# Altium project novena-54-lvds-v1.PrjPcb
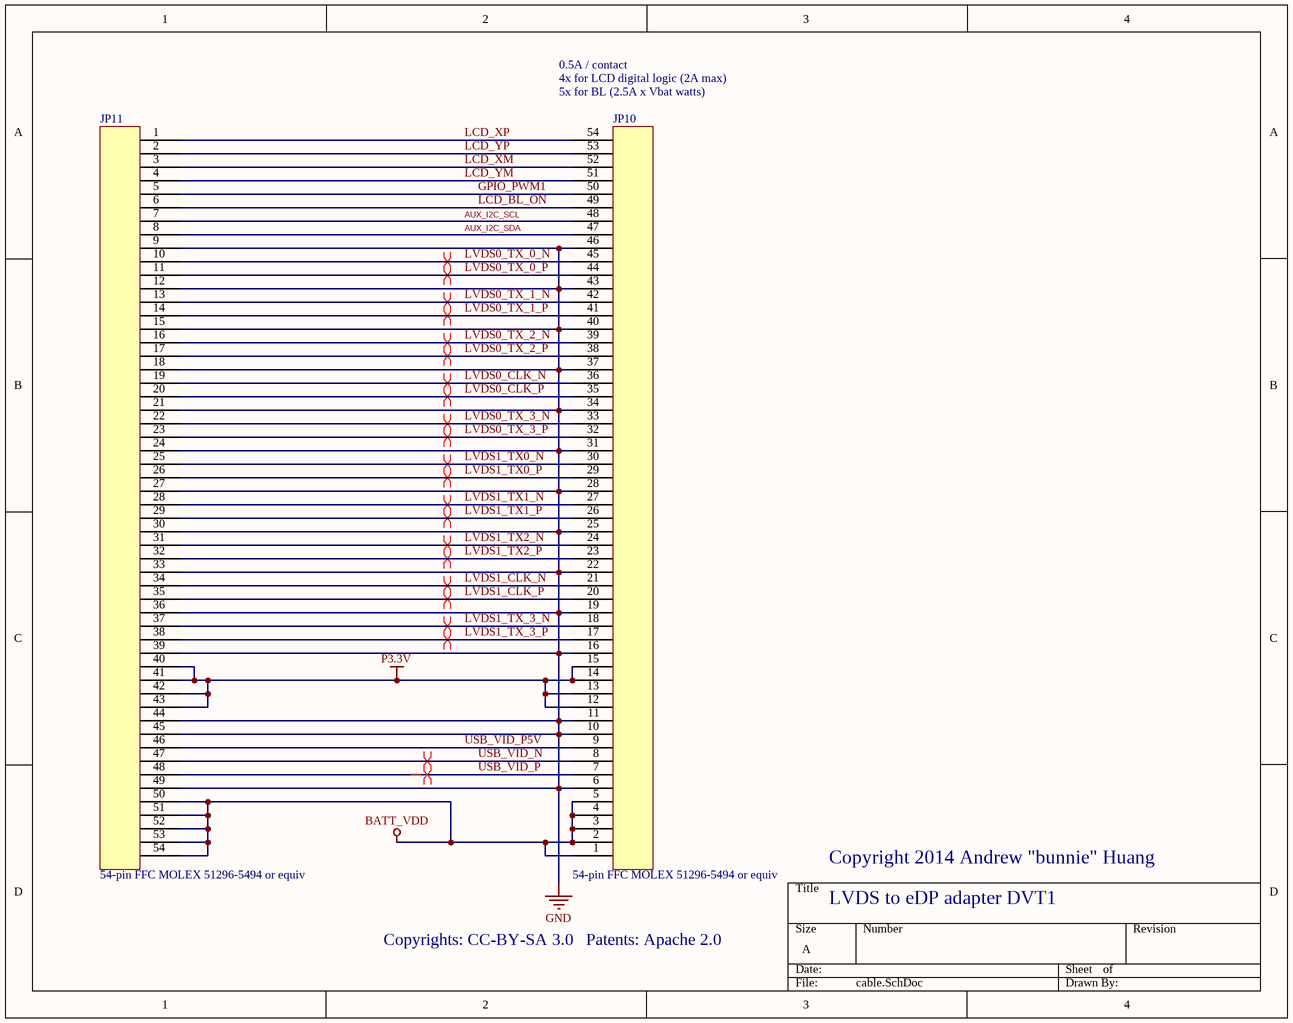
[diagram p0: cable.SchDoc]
1 sheet, 2 parts. Net scope: global (net labels, ports and power ports of the same name join across sheets).
Board file: novena-54-lvds-v2.PcbDoc

## Sheet cable.SchDoc
size A

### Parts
JP10  54-pin FFC MOLEX 51296-5494 or equiv  [FPC-54-EDGE-0.3MM]
JP11  54-pin FFC MOLEX 51296-5494 or equiv  [FPC-54-EDGE-0.3MM]

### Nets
BATT_VDD: JP10.1 JP10.2 JP10.3 JP10.4 JP10.5 JP11.50 JP11.51 JP11.52 JP11.53 JP11.54
GND: JP10.6 JP10.10 JP10.11 JP10.16 JP10.19 JP10.22 JP10.25 JP10.28 JP10.31 JP10.34 JP10.37 JP10.40 JP10.43 JP10.46 JP11.9 JP11.12 JP11.15 JP11.18 JP11.21 JP11.24 JP11.27 JP11.30 JP11.33 JP11.36 JP11.39 JP11.44 JP11.45 JP11.49
P3.3V: JP10.12 JP10.13 JP10.14 JP10.15 JP11.40 JP11.41 JP11.42 JP11.43
AUX_I2C_SCL: JP10.48 JP11.7
AUX_I2C_SDA: JP10.47 JP11.8
GPIO_PWM1: JP10.50 JP11.5
LCD_BL_ON: JP10.49 JP11.6
LCD_XM: JP10.52 JP11.3
LCD_XP: JP10.54 JP11.1
LCD_YM: JP10.51 JP11.4
LCD_YP: JP10.53 JP11.2
LVDS0_CLK_N: JP10.36 JP11.19
LVDS0_CLK_P: JP10.35 JP11.20
LVDS0_TX_0_N: JP10.45 JP11.10
LVDS0_TX_0_P: JP10.44 JP11.11
LVDS0_TX_1_N: JP10.42 JP11.13
LVDS0_TX_1_P: JP10.41 JP11.14
LVDS0_TX_2_N: JP10.39 JP11.16
LVDS0_TX_2_P: JP10.38 JP11.17
LVDS0_TX_3_N: JP10.33 JP11.22
LVDS0_TX_3_P: JP10.32 JP11.23
LVDS1_CLK_N: JP10.21 JP11.34
LVDS1_CLK_P: JP10.20 JP11.35
LVDS1_TX0_N: JP10.30 JP11.25
LVDS1_TX0_P: JP10.29 JP11.26
LVDS1_TX1_N: JP10.27 JP11.28
LVDS1_TX1_P: JP10.26 JP11.29
LVDS1_TX2_N: JP10.24 JP11.31
LVDS1_TX2_P: JP10.23 JP11.32
LVDS1_TX_3_N: JP10.18 JP11.37
LVDS1_TX_3_P: JP10.17 JP11.38
USB_VID_N: JP10.8 JP11.47
USB_VID_P: JP10.7 JP11.48
USB_VID_P5V: JP10.9 JP11.46

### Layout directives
differential pair: LVDS0_CLK_N, LVDS0_CLK_P, LVDS0_TX_0_N, LVDS0_TX_0_P, LVDS0_TX_1_N, LVDS0_TX_1_P, LVDS0_TX_2_N, LVDS0_TX_2_P, LVDS0_TX_3_N, LVDS0_TX_3_P, LVDS1_CLK_N, LVDS1_CLK_P, LVDS1_TX0_N, LVDS1_TX0_P, LVDS1_TX1_N, LVDS1_TX1_P, LVDS1_TX2_N, LVDS1_TX2_P, LVDS1_TX_3_N, LVDS1_TX_3_P, USB_VID_N, USB_VID_P

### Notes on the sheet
- 0.5A / contact
- 4x for LCD digital logic (2A max)
- (near JP10) 5x for BL (2.5A x Vbat watts)
- Copyright 2014 Andrew "bunnie" Huang
- LVDS to eDP adapter DVT1
- Copyrights: CC-BY-SA 3.0
- Patents: Apache 2.0

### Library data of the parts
JP10 JP11 = HEADER_54: Flat flex connector, 54 positions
